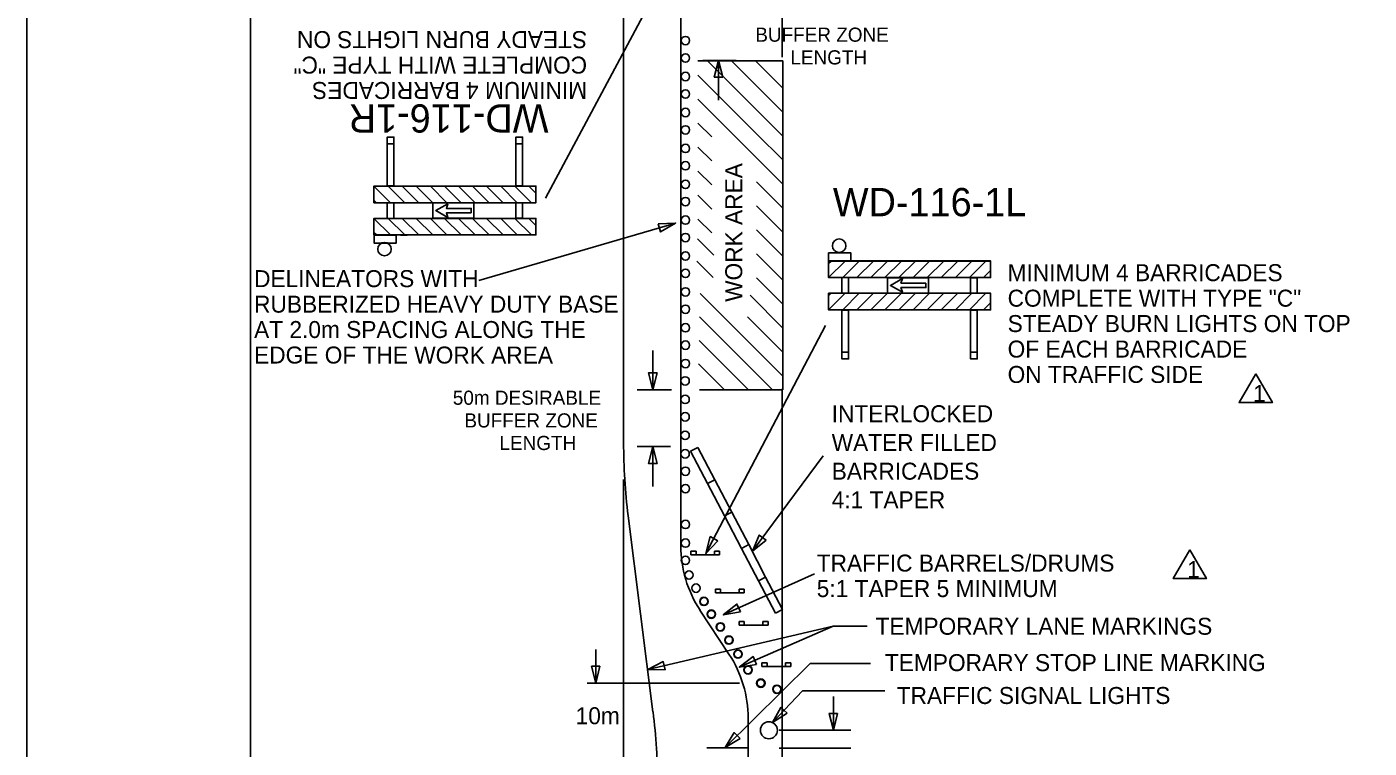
# Model space of a CAD drawing. Extents: x 2170 to 2386, y 134 to 413.
# Drawn here: x 2169.6 to 2284.4, y 290.7 to 352.3 of the extents above; entities that cross this region are included whole.
import ezdxf

# ---------------------------------------------------------------- set-up
doc = ezdxf.new("R2010")
doc.units = 0
for name, color, linetype in [('Level 1', 7, 'Continuous'), ('Level 10', 7, 'Continuous'), ('Level 2', 7, 'Continuous'), ('Level 44', 7, 'Continuous'), ('Level 5', 7, 'Continuous'), ('Level 60', 7, 'Continuous')]:
    doc.layers.add(name, color=color, linetype=linetype)

# ---------------------------------------------------------------- blocks, each defined once
blk = doc.blocks.new('BARRIC')
at = {"layer": 'Level 2'}
for p, q in [((7.12, 10.29), (8.9, 12.87)), ((8.9, 12.87), (9.45, 12.48)), ((7.67, 9.91), (9.45, 12.48)), ((3.56, 5.15), (5.34, 7.72)), ((4.12, 4.76), (5.9, 7.33)), ((0, 0), (1.78, 2.57)), ((0.56, -0.39), (2.34, 2.19)), ((0, 0), (0.56, -0.39))]:
    blk.add_line(p, q, dxfattribs=at)
at = {"layer": 'Level 44'}
for p, q in [((7.12, 10.29), (5.34, 7.72)), ((5.9, 7.33), (7.67, 9.91)), ((7.67, 9.91), (7.12, 10.29)), ((5.34, 7.72), (5.9, 7.33)), ((1.78, 2.57), (3.56, 5.15)), ((4.12, 4.76), (2.34, 2.19)), ((3.56, 5.15), (4.12, 4.76)), ((2.34, 2.19), (1.78, 2.57))]:
    blk.add_line(p, q, dxfattribs=at)
blk = doc.blocks.new('REV1')
at = {"layer": 'Level 1'}
blk.add_lwpolyline([(0.114, 1.689), (-1.305, -0.781), (1.533, -0.781)], close=True, dxfattribs=at)
blk.add_text('1', height=1.448, rotation=360, dxfattribs=at).set_placement((-0.113, -0.724))

msp = doc.modelspace()

# ---------------------------------------------------------------- linework, layer by layer
at = {"layer": 'Level 10'}
for p, q in [((2234.19, 349.72), (2234.19, 399.31)), ((2227.3, 362.59), (2213.95, 337.69)), ((2220.64, 321.3), (2220.64, 353.23)), ((2234.25, 349.42), (2226.98, 349.42)), ((2227.42, 349.46), (2230.26, 349.46)), ((2234.25, 342.99), (2227.82, 349.42)), ((2228.76, 346.05), (2228.76, 349.46)), ((2234.25, 345.04), (2229.87, 349.42)), ((2234.25, 347.09), (2231.93, 349.42)), ((2234.25, 321.3), (2234.25, 349.42)), ((2232.03, 343.15), (2226.99, 348.19)), ((2232.11, 341.02), (2226.99, 346.14)), ((2228.17, 342.91), (2226.99, 344.09)), ((2234.25, 340.94), (2232, 343.18)), ((2228.17, 340.86), (2226.99, 342.04)), ((2234.25, 338.88), (2232, 341.13)), ((2228.17, 338.81), (2226.99, 339.98)), ((2234.25, 336.83), (2232, 339.07)), ((2228.17, 336.75), (2226.99, 337.93)), ((2234.25, 334.78), (2232, 337.02)), ((2225.09, 335.54), (2208.25, 330.65)), ((2228.17, 334.7), (2226.99, 335.88)), ((2228.35, 332.8), (2226.95, 334.2)), ((2234.25, 332.73), (2232, 334.97)), ((2234.25, 330.67), (2232, 332.92)), ((2228.3, 330.88), (2226.9, 332.28)), ((2234.25, 328.62), (2232, 330.86)), ((2234.25, 322.46), (2227.18, 329.53)), ((2234.25, 326.57), (2231.45, 329.37)), ((2233.35, 321.31), (2227.14, 327.52)), ((2234.25, 324.51), (2231.24, 327.52)), ((2227.68, 307.29), (2237.91, 326.79)), ((2231.28, 321.32), (2227.09, 325.52)), ((2223.14, 321.3), (2223.14, 324.64)), ((2229.21, 321.34), (2227.04, 323.51)), ((2220.64, 316.78), (2220.64, 321.81)), ((2234.25, 321.39), (2234.16, 321.3)), ((2221.81, 321.3), (2224.74, 321.3)), ((2234.25, 321.3), (2227.13, 321.3)), ((2234.19, 178.24), (2234.19, 321.3)), ((2221.81, 316.44), (2224.65, 316.44)), ((2223.14, 313.03), (2223.14, 316.44)), ((2231.66, 307.49), (2237.7, 315.64)), ((2220.64, 178.24), (2220.64, 313.63)), ((2225.53, 313.63), (2225.53, 307.95)), ((2223.15, 293.76), (2221.04, 310.52)), ((2229.16, 302.04), (2236.95, 305.57)), ((2227.17, 302.46), (2229.65, 298.7)), ((2222.7, 297.38), (2238.55, 301.08)), ((2230.53, 297.57), (2238.55, 301.08)), ((2241.46, 301.08), (2238.55, 301.08)), ((2218.26, 299.1), (2218.26, 296.2)), ((2229.33, 290.71), (2236.58, 297.9)), ((2236.58, 297.9), (2241.75, 297.9)), ((2230.56, 296.2), (2217.53, 296.2)), ((2233.36, 292.84), (2235.94, 295.56)), ((2235.94, 295.56), (2242.97, 295.56)), ((2238.57, 295.06), (2238.57, 292.18)), ((2231.29, 178.24), (2231.29, 293.21)), ((2233.95, 292.18), (2240.06, 292.18)), ((2231.29, 290.69), (2227.75, 290.69)), ((2231.29, 290.69), (2227.75, 290.69)), ((2233.95, 290.66), (2240.06, 290.66))]:
    msp.add_line(p, q, dxfattribs=at)
for points in [[(2229.12, 348.01), (2228.76, 349.46), (2228.39, 348.01)], [(2223.6, 335.48), (2225.09, 335.54), (2223.8, 334.79)], [(2201.21, 334.52), (2199.31, 334.52), (2199.31, 333.83), (2201.21, 333.83)], [(2238.17, 332.3), (2240.07, 332.3), (2240.07, 332.99), (2238.17, 332.99)], [(2223.51, 322.75), (2223.14, 321.3), (2222.78, 322.75)], [(2223.51, 314.99), (2223.14, 316.44), (2222.78, 314.99)], [(2228.69, 308.39), (2227.68, 307.29), (2228.05, 308.74)], [(2232.82, 308.44), (2231.66, 307.49), (2232.23, 308.87)], [(2230.63, 302.3), (2229.16, 302.04), (2230.33, 302.97)], [(2232, 297.82), (2230.53, 297.57), (2231.71, 298.49)], [(2218.62, 297.65), (2218.26, 296.2), (2217.9, 297.65)], [(2224.19, 297.36), (2222.7, 297.38), (2224.03, 298.06)], [(2234.62, 293.64), (2233.36, 292.84), (2234.09, 294.14)], [(2238.93, 293.63), (2238.57, 292.18), (2238.21, 293.63)], [(2230.61, 291.48), (2229.33, 290.71), (2230.1, 291.99)]]:
    msp.add_lwpolyline(points, close=True, dxfattribs=at)
for centre, radius in [((2225.92, 351.15), 0.359), ((2225.92, 349.66), 0.359), ((2225.92, 348.08), 0.359), ((2225.92, 346.58), 0.359), ((2225.92, 345), 0.359), ((2225.92, 343.51), 0.359), ((2225.92, 341.93), 0.359), ((2225.92, 340.45), 0.359), ((2225.92, 338.86), 0.359), ((2225.92, 337.38), 0.359), ((2225.92, 335.8), 0.359), ((2225.92, 334.31), 0.359), ((2239.07, 333.61), 0.576), ((2200.2, 333.32), 0.576), ((2225.92, 332.73), 0.359), ((2225.92, 331.25), 0.359), ((2225.92, 329.66), 0.359), ((2225.92, 328.18), 0.359), ((2225.92, 326.6), 0.359), ((2225.92, 325.11), 0.359), ((2225.92, 323.53), 0.359), ((2225.9, 322.05), 0.359), ((2225.9, 320.47), 0.359), ((2225.9, 318.98), 0.359), ((2225.9, 317.4), 0.359), ((2225.9, 315.82), 0.359), ((2225.92, 314.33), 0.359), ((2225.92, 312.84), 0.359), ((2225.92, 309.78), 0.359), ((2225.92, 308.19), 0.359), ((2225.92, 306.71), 0.359), ((2226.23, 305.46), 0.359), ((2226.83, 304.33), 0.359), ((2227.51, 303.2), 0.359), ((2228.14, 302.11), 0.359), ((2228.92, 301.02), 0.359), ((2229.64, 299.89), 0.359), ((2230.42, 298.7), 0.359), ((2231.28, 297.34), 0.359), ((2232.37, 296.21), 0.359), ((2233.75, 295.69), 0.359)]:
    msp.add_circle(centre, radius, dxfattribs=at)
at = {"layer": 'Level 44'}
msp.add_circle((2233.06, 292.18), 0.726, dxfattribs=at)
at = {"layer": 'Level 5'}
for p, q in [((2225.53, 313.63), (2225.53, 360)), ((2201.01, 342.33), (2200.44, 342.33)), ((2212.01, 342.33), (2211.44, 342.33)), ((2213.15, 338.71), (2199.3, 338.71)), ((2199.3, 338.71), (2199.3, 337.29)), ((2213.15, 338.71), (2213.15, 337.29)), ((2213.15, 337.29), (2199.3, 337.29)), ((2212.01, 337.29), (2211.73, 337.29)), ((2199.3, 335.95), (2199.3, 334.53)), ((2213.15, 335.95), (2199.3, 335.95)), ((2200.44, 335.98), (2200.44, 335.95)), ((2204.36, 335.96), (2207.84, 335.96)), ((2204.36, 335.96), (2207.84, 335.96)), ((2211.44, 335.98), (2211.44, 335.95)), ((2213.15, 335.95), (2213.15, 334.53)), ((2213.15, 334.53), (2199.3, 334.53)), ((2201.57, 334.52), (2202.14, 334.52)), ((2212.01, 334.53), (2211.73, 334.53)), ((2238.16, 332.32), (2252, 332.32)), ((2238.17, 330.88), (2238.17, 332.3)), ((2240.44, 332.3), (2241, 332.3)), ((2252.01, 330.88), (2252.01, 332.3)), ((2252.01, 330.88), (2238.17, 330.88)), ((2239.3, 330.86), (2239.3, 330.88)), ((2243.22, 330.87), (2246.71, 330.87)), ((2243.22, 330.87), (2246.71, 330.87)), ((2250.31, 330.86), (2250.31, 330.88)), ((2238.17, 328.12), (2238.17, 329.54)), ((2252.01, 329.54), (2238.17, 329.54)), ((2250.87, 329.54), (2250.59, 329.54)), ((2252.01, 328.12), (2252.01, 329.54)), ((2252.01, 328.12), (2238.17, 328.12)), ((2239.87, 324.5), (2239.3, 324.5)), ((2250.87, 324.5), (2250.31, 324.5)), ((2226.83, 307.5), (2226.39, 307.5)), ((2226.39, 307.5), (2226.39, 307.19)), ((2226.39, 307.19), (2228.85, 307.19)), ((2226.83, 307.19), (2226.83, 307.5)), ((2228.85, 307.5), (2228.42, 307.5)), ((2228.42, 307.5), (2228.42, 307.19)), ((2228.85, 307.19), (2228.85, 307.5)), ((2228.93, 304.25), (2228.49, 304.25)), ((2228.49, 304.25), (2228.49, 303.94)), ((2228.93, 303.94), (2228.93, 304.25)), ((2230.95, 304.25), (2230.51, 304.25)), ((2230.51, 304.25), (2230.51, 303.94)), ((2230.95, 303.94), (2230.95, 304.25)), ((2228.49, 303.94), (2230.95, 303.94)), ((2230.96, 301.48), (2230.53, 301.48)), ((2230.53, 301.48), (2230.53, 301.18)), ((2230.53, 301.18), (2232.99, 301.18)), ((2230.96, 301.18), (2230.96, 301.48)), ((2232.99, 301.48), (2232.55, 301.48)), ((2232.55, 301.48), (2232.55, 301.18)), ((2232.99, 301.18), (2232.99, 301.48)), ((2232.9, 297.94), (2232.47, 297.94)), ((2232.47, 297.94), (2232.47, 297.63)), ((2232.47, 297.63), (2234.93, 297.63)), ((2232.9, 297.63), (2232.9, 297.94)), ((2234.93, 297.94), (2234.49, 297.94)), ((2234.49, 297.94), (2234.49, 297.63)), ((2234.93, 297.63), (2234.93, 297.94))]:
    msp.add_line(p, q, dxfattribs=at)
for points in [[(2200.44, 338.73), (2201.01, 338.73), (2201.01, 342.9), (2200.44, 342.9)], [(2211.44, 338.73), (2212.01, 338.73), (2212.01, 342.9), (2211.44, 342.9)], [(2200.72, 337.29), (2201.93, 337.29), (2200.51, 338.71), (2199.3, 338.71)], [(2203.13, 337.29), (2204.33, 337.29), (2202.91, 338.71), (2201.71, 338.71)], [(2205.54, 337.29), (2206.74, 337.29), (2205.32, 338.71), (2204.12, 338.71)], [(2207.94, 337.29), (2209.15, 337.29), (2207.73, 338.71), (2206.52, 338.71)], [(2210.35, 337.29), (2211.55, 337.29), (2210.13, 338.71), (2208.93, 338.71)], [(2212.76, 337.29), (2213.15, 337.29), (2213.15, 338.11), (2212.54, 338.71), (2211.34, 338.71)], [(2199.3, 337.29), (2199.52, 337.29), (2199.3, 337.51)], [(2200.44, 335.98), (2201.01, 335.95), (2201.01, 337.29), (2200.44, 337.29)], [(2207.84, 335.96), (2207.84, 337.29), (2204.33, 337.29), (2204.33, 335.96)], [(2207.62, 336.43), (2207.62, 336.8), (2205.49, 336.8), (2205.6, 337.2), (2204.58, 336.61), (2205.6, 336.03), (2205.49, 336.43)], [(2207.62, 336.43), (2207.62, 336.8), (2205.49, 336.8), (2205.6, 337.2), (2204.58, 336.61), (2205.6, 336.03), (2205.49, 336.43)], [(2211.44, 335.98), (2212.01, 335.98), (2212.01, 337.29), (2211.44, 337.29)], [(2200.72, 334.53), (2201.93, 334.53), (2200.51, 335.95), (2199.3, 335.95)], [(2203.13, 334.53), (2204.33, 334.53), (2202.91, 335.95), (2201.71, 335.95)], [(2205.54, 334.53), (2206.74, 334.53), (2205.32, 335.95), (2204.12, 335.95)], [(2207.94, 334.53), (2209.15, 334.53), (2207.73, 335.95), (2206.52, 335.95)], [(2210.35, 334.53), (2211.55, 334.53), (2210.13, 335.95), (2208.93, 335.95)], [(2212.76, 334.53), (2213.15, 334.53), (2213.15, 335.34), (2212.54, 335.95), (2211.34, 335.95)], [(2199.52, 334.53), (2199.3, 334.53), (2199.3, 334.74)], [(2239.58, 332.3), (2240.79, 332.3), (2239.37, 330.88), (2238.17, 330.88)], [(2238.38, 332.3), (2238.17, 332.3), (2238.17, 332.09)], [(2241.99, 332.3), (2243.19, 332.3), (2241.78, 330.88), (2240.57, 330.88)], [(2244.4, 332.3), (2245.6, 332.3), (2244.18, 330.88), (2242.98, 330.88)], [(2246.8, 332.3), (2248.01, 332.3), (2246.59, 330.88), (2245.39, 330.88)], [(2249.21, 332.3), (2250.42, 332.3), (2249, 330.88), (2247.79, 330.88)], [(2251.62, 332.3), (2252.01, 332.3), (2252.01, 331.49), (2251.4, 330.88), (2250.2, 330.88)], [(2239.3, 330.86), (2239.87, 330.88), (2239.87, 329.54), (2239.3, 329.54)], [(2246.71, 330.87), (2246.71, 329.54), (2243.19, 329.54), (2243.19, 330.87)], [(2246.48, 330.41), (2246.48, 330.03), (2244.35, 330.03), (2244.47, 329.64), (2243.45, 330.22), (2244.47, 330.81), (2244.35, 330.41)], [(2250.31, 330.86), (2250.87, 330.86), (2250.87, 329.54), (2250.31, 329.54)], [(2238.17, 329.54), (2238.38, 329.54), (2238.17, 329.32)], [(2239.58, 329.54), (2240.79, 329.54), (2239.37, 328.12), (2238.17, 328.12)], [(2241.99, 329.54), (2243.19, 329.54), (2241.78, 328.12), (2240.57, 328.12)], [(2244.4, 329.54), (2245.6, 329.54), (2244.18, 328.12), (2242.98, 328.12)], [(2246.8, 329.54), (2248.01, 329.54), (2246.59, 328.12), (2245.39, 328.12)], [(2249.21, 329.54), (2250.42, 329.54), (2249, 328.12), (2247.79, 328.12)], [(2251.62, 329.54), (2252.01, 329.54), (2252.01, 328.72), (2251.4, 328.12), (2250.2, 328.12)], [(2239.3, 328.1), (2239.87, 328.1), (2239.87, 323.93), (2239.3, 323.93)], [(2250.31, 328.1), (2250.87, 328.1), (2250.87, 323.93), (2250.31, 323.93)]]:
    msp.add_lwpolyline(points, close=True, dxfattribs=at)
for points in [[(2199.3, 338.71), (2200.72, 337.29), (2199.52, 337.29), (2199.3, 337.51), (2199.3, 338.71)], [(2201.71, 338.71), (2203.13, 337.29), (2201.93, 337.29), (2200.51, 338.71), (2201.71, 338.71)], [(2204.12, 338.71), (2205.54, 337.29), (2204.33, 337.29), (2202.91, 338.71), (2204.12, 338.71)], [(2206.52, 338.71), (2207.94, 337.29), (2206.74, 337.29), (2205.32, 338.71), (2206.52, 338.71)], [(2210.35, 337.29), (2209.15, 337.29), (2207.73, 338.71), (2208.93, 338.71), (2210.35, 337.29)], [(2212.76, 337.29), (2211.55, 337.29), (2210.13, 338.71), (2211.34, 338.71), (2212.76, 337.29)], [(2213.15, 338.11), (2212.54, 338.71), (2213.15, 338.71), (2213.15, 338.11)], [(2199.3, 335.95), (2200.72, 334.53), (2199.52, 334.53), (2199.3, 334.74), (2199.3, 335.95)], [(2201.71, 335.95), (2203.13, 334.53), (2201.93, 334.53), (2200.51, 335.95), (2201.71, 335.95)], [(2204.12, 335.95), (2205.54, 334.53), (2204.33, 334.53), (2202.91, 335.95), (2204.12, 335.95)], [(2206.52, 335.95), (2207.94, 334.53), (2206.74, 334.53), (2205.32, 335.95), (2206.52, 335.95)], [(2210.35, 334.53), (2209.15, 334.53), (2207.73, 335.95), (2208.93, 335.95), (2210.35, 334.53)], [(2212.76, 334.53), (2211.55, 334.53), (2210.13, 335.95), (2211.34, 335.95), (2212.76, 334.53)], [(2213.15, 335.34), (2212.54, 335.95), (2213.15, 335.95), (2213.15, 335.34)], [(2238.17, 330.88), (2239.58, 332.3), (2238.38, 332.3), (2238.17, 332.09), (2238.17, 330.88)], [(2240.57, 330.88), (2241.99, 332.3), (2240.79, 332.3), (2239.37, 330.88), (2240.57, 330.88)], [(2242.98, 330.88), (2244.4, 332.3), (2243.19, 332.3), (2241.78, 330.88), (2242.98, 330.88)], [(2245.39, 330.88), (2246.8, 332.3), (2245.6, 332.3), (2244.18, 330.88), (2245.39, 330.88)], [(2249.21, 332.3), (2248.01, 332.3), (2246.59, 330.88), (2247.79, 330.88), (2249.21, 332.3)], [(2251.62, 332.3), (2250.42, 332.3), (2249, 330.88), (2250.2, 330.88), (2251.62, 332.3)], [(2252.01, 331.49), (2251.4, 330.88), (2252.01, 330.88), (2252.01, 331.49)], [(2238.17, 328.12), (2239.58, 329.54), (2238.38, 329.54), (2238.17, 329.32), (2238.17, 328.12)], [(2240.57, 328.12), (2241.99, 329.54), (2240.79, 329.54), (2239.37, 328.12), (2240.57, 328.12)], [(2242.98, 328.12), (2244.4, 329.54), (2243.19, 329.54), (2241.78, 328.12), (2242.98, 328.12)], [(2245.39, 328.12), (2246.8, 329.54), (2245.6, 329.54), (2244.18, 328.12), (2245.39, 328.12)], [(2249.21, 329.54), (2248.01, 329.54), (2246.59, 328.12), (2247.79, 328.12), (2249.21, 329.54)], [(2251.62, 329.54), (2250.42, 329.54), (2249, 328.12), (2250.2, 328.12), (2251.62, 329.54)], [(2252.01, 328.72), (2251.4, 328.12), (2252.01, 328.12), (2252.01, 328.72)]]:
    msp.add_lwpolyline(points, dxfattribs=at)
for centre in [(2227.51, 303.2), (2228.14, 302.11), (2228.92, 301.02), (2229.64, 299.89), (2230.42, 298.7), (2231.28, 297.34), (2232.37, 296.21), (2233.75, 295.69)]:
    msp.add_circle(centre, 0.323, dxfattribs=at)
for centre, radius, start, end in [((2270.64, 316.78), 50, 180, 187.1968), ((2235.53, 307.95), 10, 180, 213.3066), ((2221.29, 293.21), 10, 0, 33.3066), ((2173.55, 287.5), 50, 0, 7.1968)]:
    msp.add_arc(centre, radius, start, end, dxfattribs=at)
at = {"layer": 'Level 60'}
for points in [[(2169.62, 412.76), (2385.62, 412.76), (2385.62, 133.76), (2169.62, 133.76)], [(2188.75, 401.95), (2375.62, 401.95), (2375.62, 144.57), (2188.75, 144.57)]]:
    msp.add_lwpolyline(points, close=True, dxfattribs=at)

# ---------------------------------------------------------------- block references
at = {"layer": 'Level 1'}
for p in [(2274.57, 320.98), (2268.93, 305.93)]:
    msp.add_blockref('REV1', p, dxfattribs=at)
at = {"layer": 'Level 2', "yscale": -1.0000000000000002, "rotation": -6.999999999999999}
msp.add_blockref('BARRIC', (2226.37, 316.05), dxfattribs=at)

# ---------------------------------------------------------------- texts
at = {"layer": 'Level 10'}
for s, height, rotation, p in [('STEADY BURN LIGHTS ON', 1.4514, 180, (2217.52, 351.96)), ('COMPLETE WITH TYPE "C" ', 1.4514, 180, (2217.52, 349.78)), ('MINIMUM 4 BARRICADES', 1.4514, 180, (2217.52, 347.61)), ('WD-116-1R', 2.419, 180, (2214.22, 345.7)), ('WORK AREA', 1.451, 90, (2230.78, 328.81))]:
    msp.add_text(s, height=height, rotation=rotation, dxfattribs=at).set_placement(p)
for s, height, p in [('WD-116-1L', 2.419, (2238.53, 336.13)), ('MINIMUM 4 BARRICADES', 1.4514, (2253.47, 330.58)), ('DELINEATORS WITH ', 1.451, (2189.05, 330.07)), ('RUBBERIZED HEAVY DUTY BASE ', 1.451, (2189.05, 327.89)), ('COMPLETE WITH TYPE "C" ', 1.4514, (2253.47, 328.4)), ('AT 2.0m SPACING ALONG THE ', 1.451, (2189.05, 325.72)), ('STEADY BURN LIGHTS ON TOP ', 1.4514, (2253.47, 326.23)), ('EDGE OF THE WORK AREA', 1.451, (2189.05, 323.54)), ('OF EACH BARRICADE ', 1.4514, (2253.47, 324.05)), ('ON TRAFFIC SIDE', 1.4514, (2253.47, 321.88)), ('INTERLOCKED', 1.451, (2238.43, 318.52)), ('WATER FILLED', 1.451, (2238.43, 316.06)), ('BARRICADES', 1.451, (2238.43, 313.61)), ('4:1 TAPER', 1.451, (2238.43, 311.16)), ('TRAFFIC BARRELS/DRUMS ', 1.4514, (2237.15, 305.75)), ('5:1 TAPER 5 MINIMUM', 1.4514, (2237.15, 303.57)), ('TEMPORARY LANE MARKINGS', 1.451, (2242.18, 300.35)), ('TEMPORARY STOP LINE MARKING', 1.451, (2242.98, 297.24)), ('TRAFFIC SIGNAL LIGHTS', 1.451, (2243.99, 294.43)), ('10m', 1.451, (2216.54, 292.7))]:
    msp.add_text(s, height=height, dxfattribs=at).set_placement(p)
at = {"layer": 'Level 44'}
for s, height, p in [('BUFFER ZONE', 1.2095, (2231.9, 351.05)), ('LENGTH', 1.209, (2234.9, 349.11)), ('50m DESIRABLE', 1.2095, (2206.04, 320.01)), ('BUFFER ZONE', 1.2095, (2207.03, 318.07)), ('LENGTH', 1.209, (2210.03, 316.14))]:
    msp.add_text(s, height=height, dxfattribs=at).set_placement(p)

doc.saveas('drawing.dxf')
